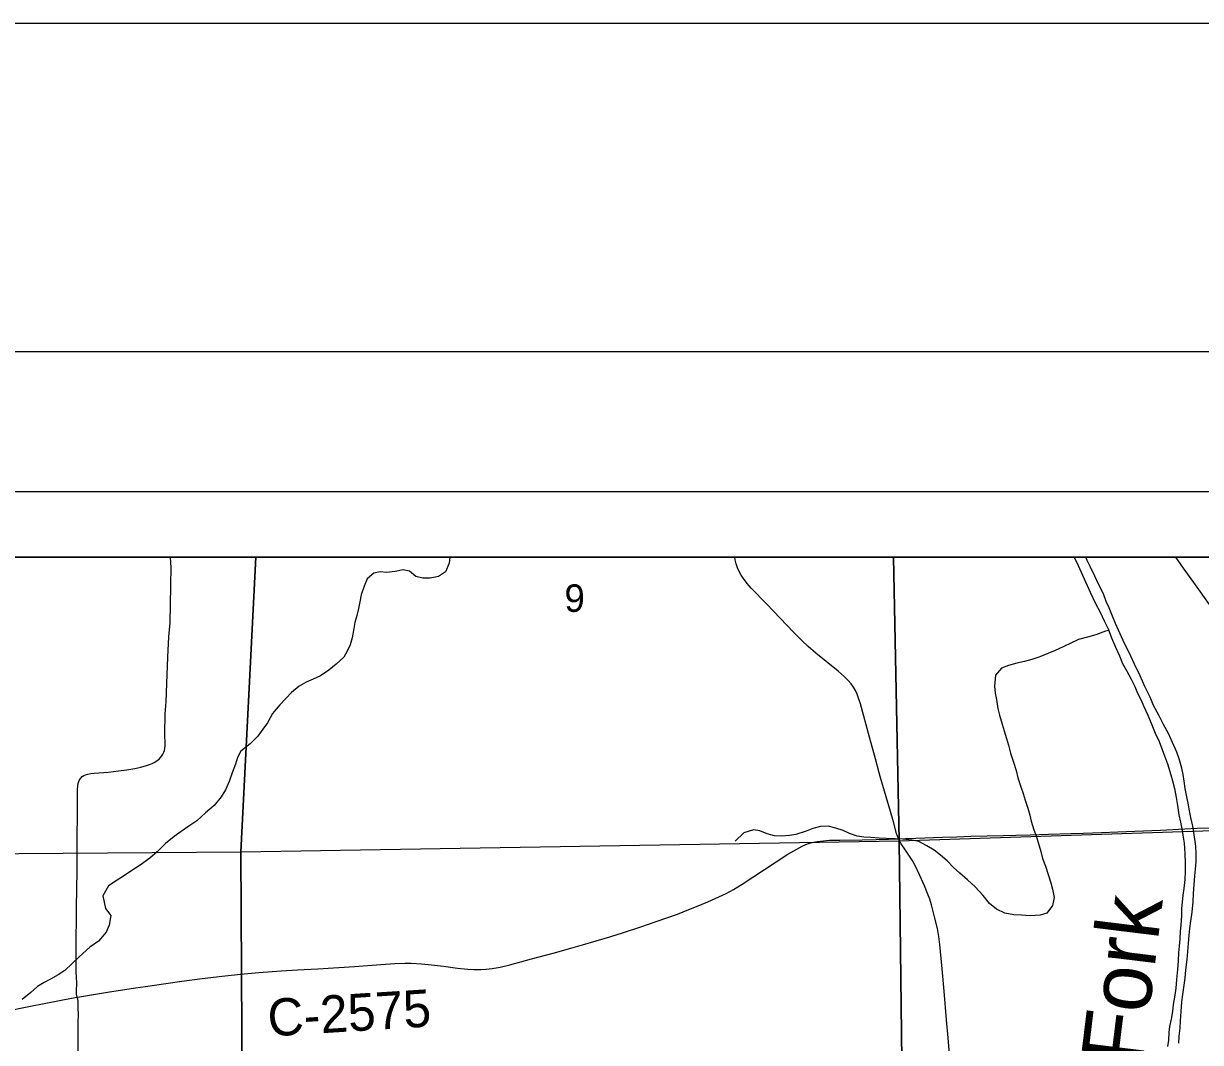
# Model space of a CAD drawing. Extents: x 0 to 34, y 0 to 22.
# Drawn here: x 5.733 to 7.526, y 20.447 to 22 of the extents above; entities that cross this region are included whole.
import ezdxf

# ---------------------------------------------------------------- set-up
doc = ezdxf.new("R2010")
doc.units = 0
for name, color, linetype in [('GM_X_County_Road', 7, 'Continuous'), ('GM_X_County_Road_Text', 7, 'Continuous'), ('GM_X_Interchange_Ramps', 7, 'Continuous'), ('GM_X_Section_Text', 7, 'Continuous'), ('GM_X_State_Location', 7, 'Continuous'), ('GM_X_State_Route', 7, 'Continuous'), ('GM_X_State_Shield', 7, 'Continuous'), ('GM_X_Township_Road', 7, 'Continuous'), ('GM_X_Unincorporated_Location', 7, 'Continuous'), ('SH_Border', 7, 'Continuous'), ('SH_Cut_Line', 7, 'Continuous'), ('SH_Data', 7, 'Continuous')]:
    doc.layers.add(name, color=color, linetype=linetype)

msp = doc.modelspace()

# ---------------------------------------------------------------- linework, layer by layer
at = {"layer": 'GM_X_County_Road'}
msp.add_lwpolyline([(7.8725, 20.5724), (7.8715, 20.5742), (7.824, 20.658), (7.7993, 20.7011), (7.7747, 20.7444), (7.7546, 20.7794), (7.7468, 20.793), (7.7453, 20.7956), (7.7234, 20.8332), (7.7041, 20.8651), (7.6814, 20.9022), (7.6667, 20.9259), (7.6194, 20.999), (7.6056, 21.0197), (7.5883, 21.0455), (7.5814, 21.0558), (7.5582, 21.0889), (7.5403, 21.1143), (7.5187, 21.1447), (7.5008, 21.17), (7.4888, 21.1866)], dxfattribs=at)
at = {"layer": 'GM_X_County_Road_Text'}
for points in [[(6.3827, 21.1866), (6.3813, 21.1774), (6.376, 21.1644), (6.3655, 21.1572), (6.3526, 21.1549), (6.3416, 21.1544), (6.331, 21.1574), (6.3211, 21.1654), (6.3112, 21.1672), (6.2995, 21.1649), (6.2862, 21.1633), (6.2764, 21.1641)], [(6.2764, 21.1641), (6.2665, 21.1625), (6.2567, 21.1537), (6.2518, 21.1423), (6.2477, 21.129), (6.2455, 21.1188), (6.2436, 21.1085), (6.2406, 21.0979), (6.238, 21.0873), (6.2362, 21.0778), (6.2336, 21.0637), (6.2306, 21.0531), (6.2261, 21.0436), (6.2208, 21.0341), (6.2095, 21.0238), (6.1982, 21.0142), (6.1857, 21.0058), (6.1743, 21.0009), (6.1637, 20.9963), (6.1528, 20.9902), (6.1415, 20.9806), (6.1324, 20.9711), (6.1237, 20.9616), (6.1124, 20.9483), (6.1049, 20.9342), (6.0977, 20.9243), (6.0902, 20.914), (6.0781, 20.9022), (6.0641, 20.8908), (6.0592, 20.8813), (6.0559, 20.8714), (6.051, 20.8577), (6.0465, 20.8448), (6.0409, 20.8319), (6.0341, 20.8212), (6.0235, 20.8083), (6.01, 20.7968), (5.9971, 20.785), (5.985, 20.7766), (5.9733, 20.7686), (5.9623, 20.761), (5.9491, 20.7503), (5.9367, 20.7377), (5.9253, 20.7278), (5.9106, 20.7171), (5.8966, 20.708), (5.8868, 20.7015), (5.8755, 20.6942), (5.8626, 20.6858), (5.8536, 20.6706), (5.8559, 20.6608), (5.8578, 20.6513), (5.8658, 20.6407), (5.8636, 20.6259), (5.8591, 20.6149), (5.8474, 20.6015), (5.8338, 20.5924), (5.8176, 20.5775), (5.8063, 20.5669), (5.7961, 20.5569), (5.7855, 20.5501), (5.7741, 20.5436), (5.7643, 20.5382), (5.7541, 20.5321), (5.7443, 20.523), (5.7307, 20.5123)], [(7.3867, 21.075), (7.3819, 21.0741), (7.3668, 21.0684), (7.3543, 21.0649), (7.3406, 21.0611), (7.3297, 21.0561), (7.3172, 21.05), (7.3051, 21.0446), (7.2941, 21.0396), (7.2816, 21.035), (7.2695, 21.0308), (7.2585, 21.0277), (7.2468, 21.025), (7.2339, 21.0216), (7.2233, 21.0173), (7.2143, 21.0067), (7.2125, 20.99), (7.2136, 20.9794), (7.2156, 20.9695), (7.2179, 20.9562), (7.2202, 20.946), (7.2244, 20.9323), (7.2275, 20.9221), (7.231, 20.9104), (7.2337, 20.9001), (7.2371, 20.888), (7.2414, 20.874), (7.2456, 20.8615), (7.2483, 20.8505), (7.2525, 20.8364), (7.2563, 20.8262), (7.2594, 20.8163), (7.2633, 20.8042), (7.2663, 20.7936), (7.2686, 20.7841), (7.2725, 20.7712), (7.2759, 20.7618), (7.279, 20.7519), (7.2832, 20.7383), (7.2859, 20.7276), (7.2901, 20.7155), (7.2986, 20.6905), (7.3009, 20.6806), (7.3036, 20.6681), (7.301, 20.6556), (7.2923, 20.6442), (7.2821, 20.6411), (7.267, 20.6399), (7.2537, 20.641), (7.2419, 20.6413), (7.2283, 20.6439), (7.2158, 20.6503), (7.2051, 20.659), (7.1952, 20.6708), (7.183, 20.684), (7.1712, 20.695), (7.1598, 20.7052), (7.1503, 20.7138), (7.1404, 20.7237), (7.1305, 20.7324), (7.1206, 20.7399), (7.1096, 20.7467), (7.0971, 20.7531), (7.0868, 20.7554), (7.0728, 20.7568), (7.0611, 20.7572), (7.0474, 20.7579), (7.0368, 20.7586), (7.0239, 20.7593), (7.0137, 20.76), (7.0031, 20.7615), (6.9917, 20.7656), (6.9818, 20.7698), (6.9708, 20.7735), (6.959, 20.7765), (6.9473, 20.7761), (6.9359, 20.773), (6.9257, 20.7692), (6.9098, 20.7642), (6.9, 20.7626), (6.8878, 20.7614), (6.8772, 20.7618), (6.8662, 20.7648), (6.8552, 20.7693), (6.8454, 20.7711), (6.8306, 20.7665), (6.8174, 20.754)]]:
    msp.add_lwpolyline(points, dxfattribs=at)
at = {"layer": 'GM_X_Interchange_Ramps'}
for points in [[(5.8145, 20.516), (5.8137, 20.5206), (5.8137, 20.5259), (5.8139, 20.5371), (5.8137, 20.5472), (5.8132, 20.5534), (5.813, 20.569), (5.813, 20.5845), (5.813, 20.6062), (5.8134, 20.6342), (5.8138, 20.6559), (5.8141, 20.6776), (5.8146, 20.7118), (5.8147, 20.737), (5.8148, 20.7564), (5.8149, 20.7704), (5.815, 20.7831), (5.8152, 20.7957), (5.8152, 20.8084), (5.8154, 20.8206), (5.8153, 20.8327), (5.8157, 20.8379), (5.8163, 20.8416), (5.8171, 20.8446), (5.8182, 20.8471), (5.8202, 20.8499), (5.8224, 20.8523), (5.8248, 20.8537), (5.8274, 20.8549), (5.8308, 20.856), (5.8353, 20.8567), (5.8408, 20.8574), (5.8622, 20.8592), (5.8777, 20.861), (5.8902, 20.8626), (5.9024, 20.8645), (5.9115, 20.8665), (5.9205, 20.869), (5.9234, 20.87), (5.9292, 20.8722), (5.9319, 20.8736), (5.9346, 20.8752), (5.9371, 20.877), (5.9395, 20.879), (5.9416, 20.8813), (5.9436, 20.8837), (5.9452, 20.8864), (5.9465, 20.8892), (5.9475, 20.8921), (5.9482, 20.8951), (5.9486, 20.8996), (5.9486, 20.9046), (5.9483, 20.914), (5.9485, 20.9225), (5.9485, 20.9292), (5.9487, 20.9362), (5.949, 20.948), (5.9502, 20.9661), (5.9513, 20.994), (5.9529, 21.034), (5.9546, 21.0652), (5.9562, 21.0868), (5.9568, 21.1146), (5.9574, 21.1424), (5.9575, 21.1546), (5.9577, 21.1608), (5.9577, 21.1701), (5.9574, 21.1794), (5.9568, 21.1856), (5.9567, 21.1866)], [(5.8161, 20.4114), (5.8161, 20.4609), (5.8164, 20.4765), (5.8165, 20.4906), (5.8164, 20.4981), (5.8163, 20.5055), (5.8161, 20.5093), (5.8156, 20.5128), (5.8145, 20.516)]]:
    msp.add_lwpolyline(points, dxfattribs=at)
at = {"layer": 'GM_X_State_Route'}
for points in [[(8.6602, 18.8038), (8.6602, 21.1866), (4.0708, 21.1866), (4.0805, 19.8173), (4.0805, 19.8117), (4.0945, 18.7432), (4.5791, 18.7479), (5.5804, 18.7605), (5.5812, 18.7605), (6.0902, 18.7638), (7.082, 18.7532), (7.9519, 18.7787), (8.0539, 18.7796), (8.5878, 18.803)], [(6.0868, 21.1866), (5.0449, 21.1866), (5.0487, 20.73), (6.064, 20.7377)], [(7.0587, 21.1866), (6.0868, 21.1866), (6.064, 20.7377), (7.0675, 20.7541)], [(8.0346, 21.1866), (7.0587, 21.1866), (7.0675, 20.7541), (8.0394, 20.7862)], [(7.0675, 20.7541), (8.0394, 20.7862), (8.0588, 19.7873), (7.0797, 19.7498)], [(6.064, 20.7377), (7.0675, 20.7541), (7.0797, 19.7498), (6.0697, 19.7327)], [(5.0487, 20.73), (6.064, 20.7377), (6.0697, 19.7327), (5.0579, 19.7292)]]:
    msp.add_lwpolyline(points, close=True, dxfattribs=at)
at = {"layer": 'GM_X_State_Shield'}
for points in [[(7.3341, 21.1866), (7.3402, 21.1738), (7.3467, 21.1594), (7.3536, 21.1435), (7.3585, 21.1332), (7.3658, 21.1173), (7.3738, 21.1029), (7.3799, 21.0897), (7.3857, 21.0775), (7.391, 21.0639), (7.3972, 21.0495), (7.4029, 21.0362), (7.4079, 21.0245), (7.4136, 21.0139), (7.4209, 21.0006), (7.4266, 20.9893), (7.4304, 20.9794), (7.4358, 20.9696), (7.44, 20.959)], [(7.51, 20.7998), (7.5077, 20.8116), (7.5057, 20.8215), (7.5034, 20.834), (7.5018, 20.845), (7.5003, 20.8556), (7.498, 20.8651), (7.4941, 20.8795), (7.4907, 20.8897), (7.4838, 20.9041), (7.4777, 20.9181), (7.47, 20.9318), (7.4632, 20.9458), (7.4551, 20.9605), (7.4498, 20.9734), (7.4417, 20.9897), (7.4345, 21.006), (7.4257, 21.0234), (7.4203, 21.0359), (7.4085, 21.0594), (7.4016, 21.0753), (7.397, 21.0856), (7.3924, 21.0969), (7.3871, 21.1094), (7.3828, 21.1193), (7.3786, 21.1306), (7.3714, 21.1447), (7.3656, 21.1575), (7.3591, 21.1716), (7.3538, 21.1814), (7.3519, 21.1866)], [(7.44, 20.959), (7.4465, 20.9457), (7.4526, 20.9309), (7.4576, 20.9184), (7.4637, 20.9055), (7.4702, 20.8881), (7.4763, 20.8718), (7.4813, 20.8551), (7.4837, 20.8457), (7.4867, 20.8339), (7.4894, 20.8206), (7.4914, 20.8081), (7.4937, 20.7941), (7.496, 20.7827), (7.498, 20.7725), (7.4995, 20.763), (7.5015, 20.7505), (7.5027, 20.7345), (7.5031, 20.7209), (7.5032, 20.7076), (7.5025, 20.6954), (7.501, 20.6814), (7.4995, 20.6715), (7.4984, 20.6609), (7.4977, 20.651), (7.4974, 20.6404), (7.4963, 20.626), (7.4956, 20.6165), (7.4949, 20.6047), (7.4938, 20.5937), (7.4931, 20.5835), (7.4924, 20.5713), (7.4913, 20.558), (7.4898, 20.5432), (7.4887, 20.5296), (7.4869, 20.5159), (7.4851, 20.5049), (7.4836, 20.4942), (7.4817, 20.4825), (7.4795, 20.4715), (7.4784, 20.462), (7.4777, 20.4506), (7.4762, 20.4407)], [(7.4933, 20.4457), (7.494, 20.4567), (7.4954, 20.4689), (7.4962, 20.4802), (7.4972, 20.4943), (7.4983, 20.5087), (7.4994, 20.5201), (7.5031, 20.5452), (7.5042, 20.5577), (7.506, 20.5733), (7.5071, 20.5858), (7.5082, 20.5976), (7.5093, 20.6105), (7.5104, 20.6207), (7.5118, 20.6321), (7.5137, 20.6454), (7.5151, 20.6613), (7.5158, 20.6739), (7.5169, 20.6879), (7.518, 20.7008), (7.5187, 20.7111), (7.5198, 20.7225), (7.5197, 20.7342), (7.5193, 20.746), (7.5177, 20.757), (7.5146, 20.7767), (7.5119, 20.79), (7.51, 20.7998)]]:
    msp.add_lwpolyline(points, dxfattribs=at)
at = {"layer": 'GM_X_Township_Road'}
for points in [[(7.0664, 20.7572), (7.0633, 20.7656), (7.0585, 20.7834), (7.0543, 20.7988), (7.0474, 20.8213), (7.0386, 20.8522), (7.0369, 20.8582), (7.0311, 20.8791), (7.0219, 20.9121), (7.0082, 20.9631), (7.0055, 20.9719), (7.0033, 20.9777), (7.0007, 20.9832), (6.9976, 20.9885), (6.9941, 20.9936), (6.9902, 20.9982), (6.9836, 21.0048), (6.9743, 21.0129), (6.9405, 21.0403), (6.9287, 21.0505), (6.9196, 21.059), (6.9065, 21.0723), (6.8657, 21.1149), (6.842, 21.1396), (6.8358, 21.1466), (6.8301, 21.1541), (6.8267, 21.1594), (6.8237, 21.1649), (6.8211, 21.1706), (6.8191, 21.1766), (6.8175, 21.1827), (6.8168, 21.1866)], [(7.0664, 20.7572), (7.0772, 20.7579), (7.0929, 20.7585), (7.1333, 20.7598), (7.155, 20.7605), (7.1767, 20.7613), (7.2016, 20.7618), (7.2264, 20.7624), (7.245, 20.7628), (7.2668, 20.7634), (7.2947, 20.7644), (7.3289, 20.7653), (7.3475, 20.766), (7.3755, 20.767), (7.4003, 20.768), (7.4656, 20.7706), (7.5028, 20.7726), (7.5215, 20.7734), (7.5619, 20.7746)], [(5.8145, 20.516), (5.818, 20.5167), (5.8333, 20.5192), (5.8608, 20.5237), (5.9037, 20.5304), (5.919, 20.5325), (5.9497, 20.5369), (5.9742, 20.5403), (6.005, 20.5443), (6.0358, 20.5482), (6.0636, 20.551), (6.0914, 20.5537), (6.1255, 20.5562), (6.1503, 20.5576), (6.1813, 20.5591), (6.2371, 20.5626), (6.2774, 20.5658), (6.299, 20.5673), (6.3145, 20.5681), (6.3238, 20.568), (6.3392, 20.567), (6.3544, 20.5655), (6.3729, 20.5632), (6.3944, 20.5604), (6.4098, 20.5587), (6.4191, 20.5581), (6.4296, 20.5582), (6.4377, 20.5587), (6.4469, 20.5597), (6.4591, 20.5619), (6.4742, 20.5654), (6.5072, 20.5742), (6.5401, 20.583), (6.5668, 20.5907), (6.5847, 20.5958), (6.6055, 20.6018), (6.6263, 20.6081), (6.6471, 20.6145), (6.6737, 20.6231), (6.6972, 20.6312), (6.7294, 20.6426), (6.7468, 20.6494), (6.7583, 20.6541), (6.7755, 20.6612), (6.7926, 20.6687), (6.8038, 20.6741), (6.8147, 20.68), (6.828, 20.6881), (6.8797, 20.7222), (6.8979, 20.734), (6.9112, 20.7418), (6.9194, 20.7461), (6.925, 20.7485), (6.9308, 20.7505), (6.9368, 20.7521), (6.9428, 20.7533), (6.9519, 20.7545), (6.9612, 20.7551), (6.9767, 20.7555), (7.0107, 20.7557), (7.0324, 20.7562), (7.051, 20.7567), (7.0664, 20.7572)], [(7.1442, 20.429), (7.1421, 20.4538), (7.1396, 20.4816), (7.1359, 20.525), (7.1328, 20.559), (7.1294, 20.5961), (7.1278, 20.6084), (7.1256, 20.6206), (7.1214, 20.6387), (7.1166, 20.6567), (7.1139, 20.6655), (7.1107, 20.6742), (7.1058, 20.6856), (7.0982, 20.7026), (7.0915, 20.7166), (7.0871, 20.7247), (7.0822, 20.7323), (7.077, 20.7401), (7.0704, 20.7496), (7.0664, 20.7572)], [(5.7083, 20.4953), (5.7387, 20.5013), (5.7692, 20.5072), (5.8058, 20.5144), (5.8145, 20.516)]]:
    msp.add_lwpolyline(points, dxfattribs=at)
at = {"layer": 'SH_Border'}
msp.add_lwpolyline([(1.5, 21.5), (33.5, 21.5), (33.5, 0.5), (1.5, 0.5)], close=True, dxfattribs=at)
at = {"layer": 'SH_Cut_Line'}
msp.add_lwpolyline([(0, 0), (34, 0), (34, 22), (0, 22)], close=True, dxfattribs=at)
at = {"layer": 'SH_Data'}
for points in [[(1.7602, 21.2866), (8.7602, 21.2866), (8.7602, 14.2866), (1.7602, 14.2866)], [(1.8602, 21.1866), (8.6602, 21.1866), (8.6602, 14.3866), (1.8602, 14.3866)]]:
    msp.add_lwpolyline(points, close=True, dxfattribs=at)

# ---------------------------------------------------------------- texts
at = {"layer": 'GM_X_Section_Text'}
msp.add_text('C-2575', height=0.05682, rotation=3.5787, dxfattribs=at).set_placement((6.1066, 20.456))
at = {"layer": 'GM_X_State_Location'}
msp.add_text('9', height=0.0419, rotation=0, dxfattribs=at).set_placement((6.5572, 21.1033))
at = {"layer": 'GM_X_Unincorporated_Location'}
msp.add_text('Lake Fork', height=0.09472, rotation=82.9891, dxfattribs=at).set_placement((7.4005, 20.1051))

doc.saveas('drawing.dxf')
